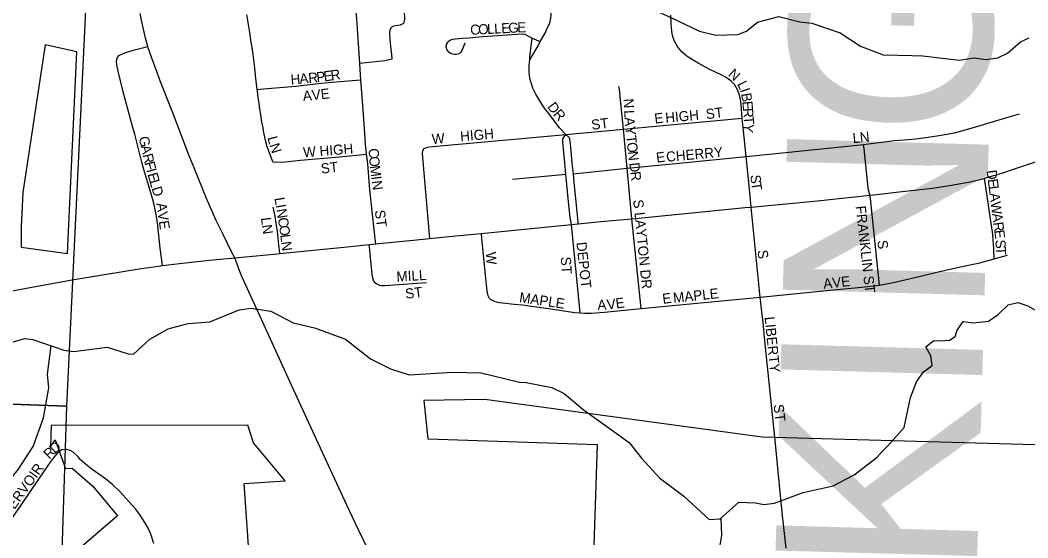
# Model space of a CAD drawing. Extents: x 0 to 34, y 0 to 22.
# Drawn here: x 27.584 to 28.529, y 17.117 to 17.603 of the extents above; entities that cross this region are included whole.
import ezdxf

# ---------------------------------------------------------------- set-up
doc = ezdxf.new("R2010")
doc.units = 0
for name, color, linetype in [('GM_X_Adjacent_County_Text', 7, 'Continuous'), ('GM_X_City_Street', 7, 'Continuous'), ('GM_X_City_Street_Text', 7, 'Continuous'), ('GM_X_Corporation', 7, 'Continuous'), ('GM_X_Minor_River', 7, 'Continuous'), ('GM_X_Section', 7, 'Continuous'), ('GM_X_State_Route', 7, 'Continuous'), ('GM_X_Township_Road', 7, 'Continuous'), ('GM_X_US_Route', 7, 'Continuous')]:
    doc.layers.add(name, color=color, linetype=linetype)

msp = doc.modelspace()

# ---------------------------------------------------------------- linework, layer by layer
at = {"layer": 'GM_X_City_Street'}
for points in [[(28.07178, 17.58311), (28.07451, 17.58769), (28.07636, 17.59097), (28.07876, 17.59615), (28.08008, 17.59897), (28.0811, 17.60192), (28.08181, 17.60495), (28.08217, 17.60803), (28.08297, 17.62338), (28.08373, 17.62944), (28.08501, 17.63543), (28.08591, 17.63834), (28.08703, 17.64116), (28.08841, 17.64386), (28.09005, 17.64643), (28.09382, 17.65128), (28.09768, 17.65622), (28.10103, 17.6615), (28.10387, 17.66708), (28.10611, 17.67292), (28.10784, 17.67893), (28.10836, 17.68164)], [(27.94276, 17.62192), (27.94298, 17.61935), (27.94431, 17.60685), (27.94453, 17.60363), (27.9435, 17.60014), (27.9403, 17.59844), (27.93417, 17.5975), (27.93196, 17.5962), (27.93068, 17.59399), (27.93028, 17.59113), (27.93068, 17.58493), (27.93168, 17.57562), (27.93229, 17.57134), (27.93254, 17.56652)], [(27.90248, 17.56245), (27.89975, 17.60452), (27.89837, 17.61827)], [(27.80615, 17.53778), (27.80488, 17.54876), (27.80351, 17.56103), (27.80195, 17.57334), (27.80059, 17.58256), (27.79924, 17.5917), (27.7966, 17.60671), (27.79636, 17.60813)], [(28.26124, 17.51127), (28.26026, 17.52357), (28.25969, 17.52854), (28.25858, 17.53386), (28.25661, 17.53831), (28.25404, 17.54259), (28.25121, 17.54551), (28.24847, 17.54774), (28.24572, 17.54953), (28.24213, 17.5515), (28.23108, 17.55685), (28.22008, 17.56263), (28.21208, 17.56748), (28.2095, 17.56931), (28.20704, 17.5713), (28.20472, 17.57347), (28.20258, 17.57582), (28.20066, 17.57837), (28.199, 17.58109), (28.19762, 17.58396), (28.19655, 17.58696), (28.19577, 17.59005), (28.19523, 17.59318), (28.1948, 17.59947), (28.19439, 17.60772)], [(28.00099, 17.58154), (27.99912, 17.57673), (27.99828, 17.57472), (27.99716, 17.57304), (27.9959, 17.57192), (27.99461, 17.57128), (27.99301, 17.57086), (27.99147, 17.5708), (27.98969, 17.57108), (27.98796, 17.57187), (27.98605, 17.57318), (27.98497, 17.5743), (27.98434, 17.57531), (27.98385, 17.57649), (27.98362, 17.57883), (27.98418, 17.58098), (27.98516, 17.58262), (27.98628, 17.58373), (27.98768, 17.58462), (27.98974, 17.58542), (27.99184, 17.58577), (27.99872, 17.58614), (28.00514, 17.58663), (28.01754, 17.58788), (28.05494, 17.59033), (28.05728, 17.58985), (28.06015, 17.58841), (28.06417, 17.58632)], [(28.06189, 17.56584), (28.06218, 17.56888), (28.06417, 17.58632)], [(28.06189, 17.56584), (28.06986, 17.57902), (28.07178, 17.58311)], [(28.06417, 17.58632), (28.07178, 17.58311)], [(27.71722, 17.37269), (27.71627, 17.37986), (27.71507, 17.38896), (27.71245, 17.41318), (27.71094, 17.42221), (27.70899, 17.4312), (27.70662, 17.44014), (27.6995, 17.46386), (27.69788, 17.46975), (27.69571, 17.47844), (27.69344, 17.48719), (27.69116, 17.49598), (27.68886, 17.5047), (27.6817, 17.53131), (27.68006, 17.53723), (27.67801, 17.54627), (27.67573, 17.55528), (27.67426, 17.5613), (27.67397, 17.56438), (27.6746, 17.56738), (27.67642, 17.56983), (27.67911, 17.57132), (27.68204, 17.57235), (27.69088, 17.57516), (27.70361, 17.57856)], [(27.93254, 17.56652), (27.92587, 17.56488), (27.90248, 17.56245)], [(28.09568, 17.49588), (28.08998, 17.50212), (28.07996, 17.51544), (28.0758, 17.52065), (28.07226, 17.52574), (28.06755, 17.53377), (28.06488, 17.53938), (28.06377, 17.54229), (28.06285, 17.54528), (28.06213, 17.54832), (28.06162, 17.5514), (28.06133, 17.55451), (28.0614, 17.56075), (28.06189, 17.56584)], [(27.90352, 17.54696), (27.90318, 17.55173), (27.90248, 17.56245)], [(27.90352, 17.54696), (27.88356, 17.54534), (27.86617, 17.54356), (27.84241, 17.54096), (27.81209, 17.53826), (27.80615, 17.53778)], [(27.90889, 17.47739), (27.90789, 17.48707), (27.90593, 17.51485), (27.90495, 17.52707), (27.90352, 17.54696)], [(27.82091, 17.47015), (27.81756, 17.47853), (27.81558, 17.48431), (27.814, 17.49021), (27.81218, 17.49912), (27.81164, 17.50202), (27.81058, 17.5078), (27.80921, 17.51657), (27.80875, 17.51942), (27.8083, 17.52221), (27.80786, 17.52488), (27.80703, 17.53057), (27.8063, 17.53655), (27.80615, 17.53778)], [(28.14982, 17.50089), (28.14683, 17.53119), (28.14637, 17.53511), (28.14604, 17.5381), (28.14553, 17.54085)], [(28.14982, 17.50089), (28.25802, 17.51097), (28.26124, 17.51127)], [(28.2651, 17.47517), (28.26321, 17.49332), (28.26124, 17.51127)], [(28.37533, 17.48641), (28.37982, 17.48703), (28.40418, 17.49003), (28.41341, 17.4907), (28.42436, 17.49171), (28.43598, 17.49328), (28.44996, 17.49545), (28.46196, 17.49781), (28.4785, 17.50234), (28.51277, 17.5128), (28.52171, 17.51525)], [(28.09568, 17.49588), (28.14982, 17.50089)], [(28.15323, 17.46426), (28.14982, 17.50089)], [(27.96217, 17.48221), (27.96497, 17.48346), (27.96797, 17.48412), (27.97778, 17.485), (28.09568, 17.49588)], [(28.09581, 17.4587), (28.09479, 17.4691), (28.09295, 17.48845), (28.0929, 17.49076), (28.0932, 17.49244), (28.09568, 17.49588)], [(28.10288, 17.45896), (28.10185, 17.46899), (28.1006, 17.48415), (28.09972, 17.49162), (28.09897, 17.4929), (28.09568, 17.49588)], [(27.96217, 17.48221), (27.96118, 17.48014), (27.96104, 17.47788), (27.96787, 17.39804)], [(28.2651, 17.47517), (28.30507, 17.47911), (28.37533, 17.48641)], [(28.3811, 17.43893), (28.38045, 17.44155), (28.38001, 17.44361), (28.37969, 17.44561), (28.37576, 17.48243), (28.37533, 17.48641)], [(27.82091, 17.47015), (27.82383, 17.46983), (27.83253, 17.47017), (27.84692, 17.4716), (27.88327, 17.47493), (27.90889, 17.47739)], [(27.91736, 17.39298), (27.91661, 17.40057), (27.9163, 17.40365), (27.91194, 17.44378), (27.90984, 17.4683), (27.90889, 17.47739)], [(28.15323, 17.46426), (28.2021, 17.46887), (28.2651, 17.47517)], [(28.26966, 17.42753), (28.26781, 17.44747), (28.2651, 17.47517)], [(28.04589, 17.45377), (28.09271, 17.45839), (28.09581, 17.4587)], [(28.10119, 17.41128), (28.10047, 17.41454), (28.09985, 17.41776), (28.09837, 17.43271), (28.09581, 17.4587)], [(28.10288, 17.45896), (28.10582, 17.45927), (28.15323, 17.46426)], [(28.10748, 17.41191), (28.10729, 17.41388), (28.10545, 17.43264), (28.10372, 17.45079), (28.10288, 17.45896)], [(28.15782, 17.41665), (28.15323, 17.46426)], [(28.49777, 17.37899), (28.4977, 17.38102), (28.49753, 17.38627), (28.49753, 17.38926), (28.49735, 17.39237), (28.497, 17.39696), (28.49646, 17.40192), (28.48874, 17.45477)], [(28.3901, 17.35447), (28.38179, 17.4358), (28.3811, 17.43893)], [(27.82732, 17.38392), (27.82659, 17.3922), (27.82579, 17.39861), (27.82519, 17.40511), (27.82409, 17.41212), (27.82289, 17.41923), (27.82199, 17.42323), (27.82129, 17.42754)], [(28.27836, 17.34298), (28.27472, 17.37733), (28.26966, 17.42753)], [(28.16651, 17.33254), (28.15782, 17.41665)], [(28.0162, 17.40289), (28.01662, 17.39857), (28.01969, 17.36689), (28.02033, 17.36079), (28.02099, 17.35476), (28.02158, 17.34858), (28.02225, 17.34574), (28.02263, 17.34453), (28.02317, 17.34333), (28.0239, 17.34219), (28.02493, 17.34124), (28.0261, 17.34047), (28.02744, 17.3398), (28.03037, 17.3388), (28.03342, 17.33817), (28.0365, 17.33772), (28.04718, 17.33657), (28.05506, 17.33573), (28.0796, 17.33232), (28.08576, 17.33149), (28.10416, 17.32875), (28.10939, 17.32834)], [(28.10939, 17.32834), (28.10119, 17.41128)], [(27.965, 17.35647), (27.92583, 17.35376), (27.923, 17.35377), (27.92121, 17.35405), (27.91992, 17.35454), (27.91844, 17.35537), (27.91731, 17.35632), (27.91619, 17.35751), (27.91537, 17.3588), (27.91471, 17.36103), (27.91411, 17.36512), (27.91334, 17.37096), (27.91298, 17.37394), (27.91172, 17.38723), (27.91123, 17.39236)], [(28.3901, 17.35447), (28.40465, 17.35709), (28.42864, 17.36286), (28.44662, 17.36713), (28.4707, 17.37239), (28.48449, 17.37525), (28.49777, 17.37899)], [(28.49777, 17.37899), (28.51049, 17.38257)], [(28.27836, 17.34298), (28.34693, 17.35007), (28.37363, 17.3525), (28.3901, 17.35447)], [(28.16651, 17.33254), (28.27836, 17.34298)], [(28.28202, 17.30817), (28.28121, 17.31605), (28.27836, 17.34298)], [(28.10939, 17.32834), (28.11345, 17.32802), (28.11964, 17.32812), (28.13204, 17.32903), (28.16651, 17.33254)], [(28.29218, 17.2087), (28.29189, 17.21163), (28.28202, 17.30817)], [(27.62652, 17.20006), (27.62586, 17.20012), (27.62291, 17.19958), (27.62131, 17.19881), (27.62059, 17.19834), (27.61835, 17.19617), (27.61634, 17.19383), (27.61258, 17.18896), (27.60546, 17.17894), (27.59339, 17.16115), (27.58293, 17.14602), (27.57603, 17.13631)]]:
    msp.add_lwpolyline(points, dxfattribs=at)
at = {"layer": 'GM_X_Corporation'}
msp.add_lwpolyline([(27.58455, 17.38987), (27.62822, 17.38406), (27.63673, 17.57327), (27.60716, 17.58005), (27.58632, 17.4413), (27.58455, 17.40924)], close=True, dxfattribs=at)
msp.add_lwpolyline([(27.58455, 17.38987), (27.62822, 17.38406), (27.63673, 17.57327), (27.60716, 17.58005), (27.58632, 17.4413), (27.58455, 17.40924)], close=True, dxfattribs=at)
for points in [[(28.53589, 17.20451), (28.28012, 17.21166), (28.01974, 17.24688), (27.96242, 17.24597), (27.96618, 17.21017), (28.12517, 17.2046), (28.11958, 17.0337)], [(28.53589, 17.20451), (28.28012, 17.21166), (28.01974, 17.24688), (27.96242, 17.24597), (27.96618, 17.21017), (28.12517, 17.2046), (28.11958, 17.0337)], [(27.80448, 17.01542), (27.79382, 17.16795), (27.8325, 17.17065), (27.80262, 17.20626), (27.79721, 17.22292), (27.61271, 17.22256), (27.61231, 17.2025), (27.61665, 17.20915), (27.62636, 17.18226), (27.63241, 17.18262), (27.6518, 17.16567), (27.67509, 17.13775), (27.63038, 17.09911)], [(27.80448, 17.01542), (27.79382, 17.16795), (27.8325, 17.17065), (27.80262, 17.20626), (27.79721, 17.22292), (27.61271, 17.22256), (27.61231, 17.2025), (27.61665, 17.20915), (27.62636, 17.18226), (27.63241, 17.18262), (27.6518, 17.16567), (27.67509, 17.13775), (27.63038, 17.09911)]]:
    msp.add_lwpolyline(points, dxfattribs=at)
at = {"layer": 'GM_X_Minor_River'}
for points in [[(28.17818, 17.61303), (28.20023, 17.60293), (28.22115, 17.59283), (28.23671, 17.58915), (28.25717, 17.58967), (28.26548, 17.59277), (28.27565, 17.60119), (28.29569, 17.60665), (28.31544, 17.60148), (28.32681, 17.60042), (28.35341, 17.59112), (28.37245, 17.57873), (28.39373, 17.57053), (28.42102, 17.56996), (28.43087, 17.56965), (28.46501, 17.56572), (28.47901, 17.56772), (28.49001, 17.56628), (28.50137, 17.56788), (28.51043, 17.57212), (28.52247, 17.58283), (28.53078, 17.58669)], [(27.572, 17.2997), (27.58788, 17.30437), (27.59547, 17.30328), (27.62472, 17.29324), (27.63383, 17.29217), (27.66525, 17.29619), (27.685, 17.28987), (27.68993, 17.28953), (27.70535, 17.30368), (27.72271, 17.3133), (27.72952, 17.31525), (27.74124, 17.31837), (27.76169, 17.32003), (27.78927, 17.33124), (27.80062, 17.33283), (27.81883, 17.32993), (27.83976, 17.31907), (27.85988, 17.31428), (27.88914, 17.30348), (27.91239, 17.28504), (27.93141, 17.27569), (27.94888, 17.27012), (27.98941, 17.27268), (28.01632, 17.27212), (28.05238, 17.26326), (28.05845, 17.26293), (28.08273, 17.25817), (28.09415, 17.25255), (28.11207, 17.2375), (28.15512, 17.20667), (28.16698, 17.19195), (28.18418, 17.1731), (28.20666, 17.15617), (28.23032, 17.13432), (28.24055, 17.13478), (28.25824, 17.15047), (28.27378, 17.14982), (28.28175, 17.14836), (28.29159, 17.14957), (28.31842, 17.15963), (28.34679, 17.1659), (28.36642, 17.17629), (28.38789, 17.19277), (28.39278, 17.19812), (28.39804, 17.20347), (28.41344, 17.22066), (28.41929, 17.24879), (28.42487, 17.26364), (28.43162, 17.2728), (28.43953, 17.27893), (28.43832, 17.28803), (28.43371, 17.29635), (28.44124, 17.30248), (28.44731, 17.30214), (28.45602, 17.30258), (28.4613, 17.30604), (28.46315, 17.31212), (28.46877, 17.32014), (28.47825, 17.31907), (28.49264, 17.32068), (28.50169, 17.32682), (28.51109, 17.336), (28.52017, 17.33797), (28.52929, 17.33499), (28.54032, 17.32862)], [(27.53253, 17.10885), (27.53622, 17.1214), (27.56363, 17.15538), (27.56886, 17.16529), (27.58199, 17.18171), (27.59585, 17.20269), (27.6055, 17.22971), (27.61059, 17.25784), (27.60936, 17.27073), (27.61283, 17.29732)], [(28.24124, 17.13539), (28.2418, 17.1196), (28.23818, 17.09718)]]:
    msp.add_lwpolyline(points, dxfattribs=at)
at = {"layer": 'GM_X_Section'}
msp.add_lwpolyline([(26.67748, 18.31474), (27.6773, 18.28453), (27.62712, 17.24067), (26.63943, 17.27671)], close=True, dxfattribs=at)
msp.add_lwpolyline([(27.10364, 16.25426), (26.60351, 16.27226), (26.63943, 17.27671), (27.62712, 17.24067), (27.60079, 16.42084)], dxfattribs=at)
at = {"layer": 'GM_X_State_Route'}
for points in [[(27.78511, 17.37987), (27.78249, 17.38492), (27.7741, 17.40198), (27.76726, 17.41557), (27.75871, 17.43557), (27.74696, 17.46434), (27.74225, 17.47581), (27.72704, 17.51618), (27.7155, 17.54519), (27.71225, 17.5539), (27.707, 17.56848), (27.70397, 17.57732), (27.70361, 17.57856), (27.70135, 17.58632), (27.69796, 17.60151), (27.69629, 17.60955)], [(27.99296, 16.97683), (27.98481, 16.98737), (27.96828, 17.00993), (27.95579, 17.02773), (27.94569, 17.04339), (27.93278, 17.06463), (27.92358, 17.08084), (27.91389, 17.09926), (27.912, 17.10284), (27.901, 17.12514), (27.89039, 17.14763), (27.86559, 17.20127), (27.83822, 17.26056), (27.80722, 17.32841), (27.79176, 17.3624), (27.7897, 17.36729), (27.78511, 17.37987)]]:
    msp.add_lwpolyline(points, dxfattribs=at)
at = {"layer": 'GM_X_Township_Road'}
for points in [[(28.30247, 17.10751), (28.29941, 17.13537), (28.2967, 17.16322), (28.29218, 17.2087)], [(27.7092, 17.11164), (27.70631, 17.12046), (27.70383, 17.12616), (27.70076, 17.13158), (27.69558, 17.13932), (27.69183, 17.14428), (27.68574, 17.15133), (27.67734, 17.16046), (27.6708, 17.1669), (27.66853, 17.16883), (27.66381, 17.17251), (27.65129, 17.18132), (27.64668, 17.18496), (27.64011, 17.19072), (27.63799, 17.19305), (27.63339, 17.19741), (27.6307, 17.19907), (27.62758, 17.19996), (27.62652, 17.20006)]]:
    msp.add_lwpolyline(points, dxfattribs=at)
at = {"layer": 'GM_X_US_Route'}
for points in [[(27.82732, 17.38392), (27.89386, 17.39063), (27.91123, 17.39236), (27.91736, 17.39298), (27.95871, 17.39711), (27.96787, 17.39804), (27.99267, 17.40057), (28.0162, 17.40289), (28.10119, 17.41128), (28.10748, 17.41191), (28.12854, 17.41399), (28.15782, 17.41665), (28.26427, 17.42712), (28.26966, 17.42753), (28.33195, 17.43347), (28.37842, 17.43867), (28.3811, 17.43893), (28.38763, 17.43957), (28.40597, 17.44154), (28.44006, 17.44542), (28.45601, 17.44777), (28.47543, 17.45127), (28.48595, 17.45397), (28.48874, 17.45477), (28.49838, 17.45753), (28.50501, 17.45961), (28.51785, 17.46372), (28.53652, 17.47)], [(27.78511, 17.37987), (27.79504, 17.38081), (27.82188, 17.38337), (27.82732, 17.38392)], [(27.46011, 17.32793), (27.49694, 17.33455), (27.53861, 17.34222), (27.59798, 17.35315), (27.6307, 17.35887), (27.66276, 17.36448), (27.69723, 17.36996), (27.71118, 17.37193), (27.71722, 17.37269), (27.73328, 17.3747), (27.76143, 17.37765), (27.78511, 17.37987)]]:
    msp.add_lwpolyline(points, dxfattribs=at)

# ---------------------------------------------------------------- texts
at = {"layer": 'GM_X_Adjacent_County_Text'}
for s, rotation, p in [('G', 88.38934, (28.49288, 17.49145)), ('N', 88.40347, (28.48821, 17.32403)), ('I', 88.40402, (28.48605, 17.24656)), ('K', 88.40513, (28.48139, 17.07912))]:
    msp.add_text(s, height=0.18939, rotation=rotation, dxfattribs=at).set_placement(p)
at = {"layer": 'GM_X_City_Street_Text'}
for s, height, rotation, p in [('E', 0.00947, 2.91661, (28.03542, 17.59076)), ('G', 0.00947, 2.9243, (28.04208, 17.5911)), ('E', 0.00947, 1.9674, (28.05036, 17.59153)), ('C', 0.00947, 2.91577, (28.00629, 17.58928)), ('O', 0.00947, 2.9243, (28.01378, 17.58966)), ('L', 0.00947, 2.91661, (28.0221, 17.59009)), ('L', 0.00947, 2.89789, (28.02876, 17.59043)), ('R', 0.00947, 5.07852, (27.85451, 17.54408)), ('P', 0.00947, 6.42137, (27.86222, 17.54477)), ('E', 0.00947, 7.93691, (27.86911, 17.54555)), ('R', 0.00947, 8.16568, (27.87576, 17.54647)), ('N', 0.00947, 318.97443, (28.24748, 17.5514)), ('H', 0.00947, 5.07574, (27.8379, 17.54261)), ('A', 0.00947, 5.05397, (27.8462, 17.54335)), ('L', 0.00947, 295.8321, (28.2563, 17.54333)), ('A', 0.00947, 5.23203, (27.84937, 17.52722)), ('V', 0.00947, 5.54992, (27.85773, 17.52799)), ('E', 0.00947, 7.04762, (27.86629, 17.52882)), ('I', 0.00947, 288.14454, (28.25908, 17.53764)), ('B', 0.00947, 278.87542, (28.26028, 17.53407)), ('D', 0.00947, 307.06223, (28.07795, 17.5217)), ('N', 0.00947, 273.41138, (28.14983, 17.52927)), ('E', 0.00947, 274.81356, (28.26142, 17.52684)), ('R', 0.00947, 311.40095, (28.08346, 17.51446)), ('L', 0.00947, 273.4299, (28.15047, 17.51845)), ('E', 0.00947, 7.11829, (28.1795, 17.50593)), ('HIGH', 0.00947, 5.08186, (28.18956, 17.50678)), ('ST', 0.00947, 7.11829, (28.22782, 17.51011)), ('R', 0.00947, 274.76567, (28.26198, 17.5202)), ('ST', 0.00947, 7.12165, (28.12033, 17.5001)), ('A', 0.00947, 273.52357, (28.15087, 17.51178)), ('T', 0.00947, 274.81563, (28.2626, 17.51271)), ('W', 0.00947, 4.39613, (27.97041, 17.48678)), ('HIGH', 0.00947, 4.9021, (27.99706, 17.48928)), ('Y', 0.00947, 275.60719, (28.15142, 17.50309)), ('Y', 0.00947, 262.41402, (28.26317, 17.50661)), ('L', 0.00947, 5.03125, (28.36541, 17.48761)), ('N', 0.00947, 6.08583, (28.37224, 17.48821)), ('G', 0.00947, 283.27808, (27.69479, 17.49291)), ('L', 0.00947, 284.86455, (27.81564, 17.49284)), ('N', 0.00947, 287.7637, (27.81749, 17.4859)), ('W HIGH', 0.00947, 4.48569, (27.8496, 17.47428)), ('T', 0.00947, 276.74747, (28.15226, 17.49459)), ('O', 0.00947, 276.76613, (28.15304, 17.48797)), ('A', 0.00947, 283.27306, (27.6967, 17.4848)), ('R', 0.00947, 283.23496, (27.69861, 17.47669)), ('C', 0.00947, 273.45061, (27.91067, 17.4826)), ('N', 0.00947, 276.79173, (28.15402, 17.47969)), ('E', 0.00947, 7.11829, (28.18116, 17.46927)), ('CHERRY', 0.00947, 5.10327, (28.19039, 17.47011)), ('F', 0.00947, 284.07305, (27.70036, 17.46924)), ('ST', 0.00947, 7.12165, (27.86652, 17.45894)), ('O', 0.00947, 274.63255, (27.91113, 17.4749)), ('D', 0.00947, 276.76613, (28.1553, 17.46893)), ('I', 0.00947, 285.11976, (27.70203, 17.4626)), ('E', 0.00947, 285.53616, (27.70314, 17.4585)), ('M', 0.00947, 277.33654, (27.91186, 17.46611)), ('R', 0.00947, 276.78133, (28.15627, 17.46065)), ('D', 0.00947, 277.27686, (28.49065, 17.4619)), ('L', 0.00947, 285.71292, (27.70493, 17.45205)), ('I', 0.00947, 277.56343, (27.91314, 17.45615)), ('N', 0.00947, 277.58778, (27.91369, 17.45202)), ('S', 0.00947, 275.25382, (28.269, 17.45763)), ('T', 0.00947, 278.00012, (28.26967, 17.4505)), ('E', 0.00947, 277.28574, (28.49171, 17.45363)), ('D', 0.00947, 287.84312, (27.70685, 17.44526)), ('L', 0.00947, 277.28574, (28.49256, 17.44702)), ('A', 0.00947, 277.27686, (28.4934, 17.4404)), ('AVE', 0.00947, 277.85434, (27.71148, 17.4311)), ('L', 0.00947, 279.21978, (27.82232, 17.43607)), ('S LAYTON DR', 0.0094697, 275.64996, (28.15899, 17.43435)), ('W', 0.00947, 277.3123, (28.49446, 17.43213)), ('I', 0.00947, 279.13173, (27.82339, 17.42949)), ('N', 0.00947, 279.22199, (27.82405, 17.42536)), ('ST', 0.00947, 277.12166, (27.91649, 17.42439)), ('FRANKLIN ST', 0.0094697, 276.33674, (28.3678, 17.4284)), ('A', 0.00947, 277.27686, (28.49584, 17.42139)), ('L', 0.00947, 276.79286, (27.80965, 17.41749)), ('C', 0.00947, 279.21881, (27.82538, 17.41714)), ('R', 0.00947, 277.25758, (28.49689, 17.41312)), ('N', 0.00947, 278.32275, (27.81047, 17.4106)), ('O', 0.00947, 278.29085, (27.82658, 17.40977)), ('E', 0.00947, 277.06741, (28.49784, 17.40569)), ('L', 0.00947, 277.17585, (27.82778, 17.40157)), ('N', 0.00947, 277.10062, (27.82861, 17.39496)), ('DEPOT', 0.00947, 276.33647, (28.10566, 17.39437)), ('S', 0.00947, 277.12166, (28.38815, 17.39605)), ('S', 0.00947, 273.77229, (28.49889, 17.39673)), ('W', 0.00947, 274.39743, (28.02066, 17.38514)), ('S', 0.00947, 277.12166, (28.27565, 17.38689)), ('T', 0.00947, 272.8979, (28.49932, 17.39012)), ('ST', 0.00947, 273.57465, (28.09107, 17.38077)), ('MILL', 0.00947, 3.3706, (27.93711, 17.35761)), ('AVE', 0.00947, 5.91051, (28.33787, 17.35094)), ('ST', 0.00947, 7.1351, (27.94569, 17.34144)), ('MAPLE', 0.00947, 351.52837, (28.05164, 17.33843)), ('E', 0.00947, 7.12502, (28.187, 17.33677)), ('MAPLE', 0.00947, 6.07412, (28.19703, 17.33761)), ('A', 0.00947, 2.49335, (28.12566, 17.33095)), ('V', 0.00947, 6.88078, (28.13477, 17.33138)), ('E', 0.00947, 7.42385, (28.14313, 17.33239)), ('LIBERTY', 0.00947, 275.80338, (28.28232, 17.32435)), ('ST', 0.00947, 277.11998, (28.29066, 17.24189)), ('D', 0.00947, 43.22216, (27.61637, 17.19551)), ('R', 0.00947, 43.21437, (27.61091, 17.19038)), ('RESERVOIR', 0.00947, 54.71538, (27.56327, 17.12187))]:
    msp.add_text(s, height=height, rotation=rotation, dxfattribs=at).set_placement(p)

doc.saveas('drawing.dxf')
